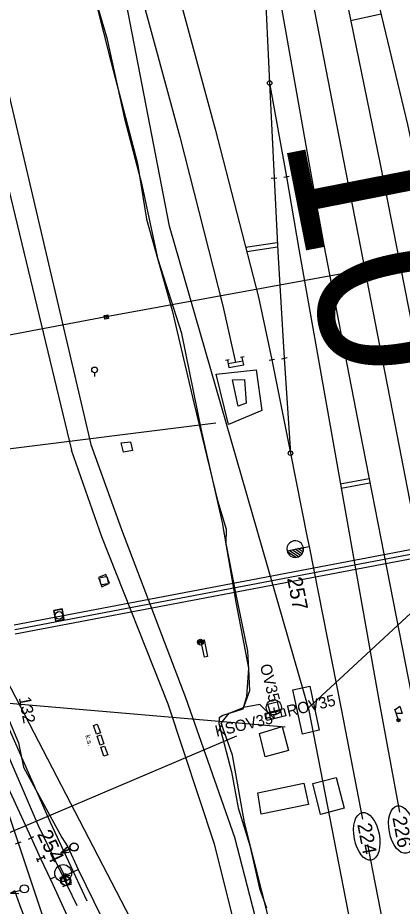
# Model space of a CAD drawing. Extents: x -545846 to -545044, y -1122650 to -1119108.
# Drawn here: x -545623.5 to -545572.5, y -1119607 to -1119489.2 of the extents above; entities that cross this region are included whole.
import ezdxf

# ---------------------------------------------------------------- set-up
doc = ezdxf.new("R2010")
doc.units = 0
for name, color, linetype in [('osvětlené plochy-hodnota-obrys', 7, 'Continuous'), ('Vrstva 1', 7, 'Continuous'), ('Vrstva 1 - Koleje', 7, 'Continuous'), ('Vrstva 11 - Trakce', 7, 'Continuous'), ('Vrstva 12', 7, 'Continuous'), ('Vrstva 12 - Trakce zaklady', 7, 'Continuous'), ('Vrstva 15', 7, 'Continuous'), ('Vrstva 19', 7, 'Continuous'), ('Vrstva 2', 7, 'Continuous'), ('Vrstva 2 - Vyhybky', 7, 'Continuous'), ('Vrstva 23', 7, 'Continuous'), ('Vrstva 25', 7, 'Continuous'), ('Vrstva 26', 7, 'Continuous'), ('Vrstva 27', 7, 'Continuous'), ('Vrstva 28 - zabzar', 7, 'Continuous'), ('Vrstva 3', 7, 'Continuous'), ('Vrstva 3 - Lisy - Pocitaci body', 7, 'Continuous'), ('Vrstva 31', 7, 'Continuous'), ('Vrstva 33', 7, 'Continuous'), ('Vrstva 36', 7, 'Continuous'), ('Vrstva 4 - Teren - stezky - prechody - plochy', 7, 'Continuous'), ('Vrstva 41', 7, 'Continuous'), ('Vrstva 43', 7, 'Continuous'), ('Vrstva 47', 7, 'Continuous'), ('Vrstva 51', 7, 'Continuous'), ('Vrstva 63', 7, 'Continuous'), ('Vrstva 7', 7, 'Continuous')]:
    doc.layers.add(name, color=color, linetype=linetype)

msp = doc.modelspace()

# ---------------------------------------------------------------- linework, layer by layer
at = {"layer": 'osvětlené plochy-hodnota-obrys'}
msp.add_line((-545562.16, -1119697.71), (-545631.88, -1119563.68), dxfattribs=at)
for points in [[(-545584.85, -1119581.02), (-545603.39, -1119516.8), (-545628.87, -1119385.18)], [(-545520.95, -1119506.89), (-545547.77, -1119546.31), (-545584.96, -1119580.66)], [(-545441.66, -1120319.91), (-545444.67, -1120302.28), (-545584.85, -1119581.02)]]:
    msp.add_lwpolyline(points, dxfattribs=at)
at = {"layer": 'Vrstva 1'}
msp.add_line((-545588.16, -1119534.32), (-545587.33, -1119546.92), dxfattribs=at)
for points in [[(-545599.51, -1119416.9), (-545596.69, -1119429.21), (-545596.41, -1119430.45), (-545593.93, -1119441.54), (-545591.16, -1119453.96), (-545590.21, -1119458.42), (-545589.95, -1119459.65), (-545585, -1119483.93), (-545580.04, -1119509.49), (-545578.33, -1119518.28), (-545575.84, -1119531.04)], [(-545620.21, -1119419.86), (-545619.43, -1119422.68), (-545612.37, -1119448.5), (-545606.52, -1119470.01), (-545604.5, -1119477.4), (-545597.32, -1119503.97), (-545591.58, -1119526.22), (-545589.81, -1119534.53)], [(-545624.75, -1119421.28), (-545624.13, -1119423.57), (-545617.27, -1119448.91), (-545611.27, -1119470.9), (-545609.21, -1119478.48), (-545602.01, -1119504.99), (-545596.3, -1119527.38), (-545594.62, -1119534.89)], [(-545593.93, -1119441.54), (-545592.82, -1119454.17), (-545592.44, -1119458.53), (-545592.33, -1119459.79), (-545592.3, -1119460.15), (-545592.2, -1119461.35), (-545591.2, -1119472.71), (-545589.02, -1119485.12), (-545584.57, -1119510.35), (-545582.9, -1119519.35), (-545580.39, -1119532.39)], [(-545589, -1119445.3), (-545586.24, -1119457.51), (-545586.1, -1119458.13), (-545580.77, -1119482.71), (-545575.45, -1119508.59), (-545573.77, -1119517.07), (-545571.21, -1119530.11)], [(-545580.06, -1119469.46), (-545577.13, -1119481.19), (-545571.82, -1119503.35), (-545568.95, -1119516.79), (-545566.49, -1119529.08)], [(-545591.2, -1119472.71), (-545590.69, -1119485.25), (-545590.64, -1119486.5), (-545590.1, -1119497.85), (-545589.52, -1119510.43), (-545589.02, -1119520.21), (-545588.16, -1119534.32)], [(-545590.1, -1119497.85), (-545587.86, -1119510.29), (-545586.21, -1119519.87), (-545583.87, -1119533.1)], [(-545575.84, -1119531.04), (-545573.5, -1119543.05), (-545570.17, -1119560.16), (-545566.74, -1119577.79), (-545563.84, -1119592.72)], [(-545583.87, -1119533.1), (-545581.83, -1119544.78), (-545578.74, -1119562.22), (-545575.63, -1119579.63), (-545572.9, -1119594.48)], [(-545580.39, -1119532.39), (-545578.14, -1119544.01), (-545574.96, -1119560.25), (-545571.36, -1119578.75), (-545568.45, -1119593.62)], [(-545589.81, -1119534.53), (-545587.33, -1119546.92), (-545585.11, -1119558.07), (-545584.87, -1119559.26)], [(-545584.87, -1119559.26), (-545580.63, -1119580.79), (-545577.77, -1119595.43)], [(-545577.12, -1119598.78), (-545576.45, -1119602.24), (-545572.16, -1119624.17), (-545568.47, -1119643.08), (-545563.87, -1119666.71), (-545559.47, -1119689.27)], [(-545619.18, -1119603.36), (-545619.11, -1119603.5)], [(-545619.12, -1119603.52), (-545618.83, -1119604.09), (-545613.93, -1119614.83), (-545607.84, -1119629.66)]]:
    msp.add_lwpolyline(points, dxfattribs=at)
for centre in [(-545572.58, -1119596.8), (-545577.23, -1119597.7)]:
    msp.add_ellipse(centre, major_axis=(0.61, -3.15), ratio=0.521067, dxfattribs=at)
at = {"layer": 'Vrstva 1 - Koleje'}
for points in [[(-545633.92, -1119567.08), (-545633.67, -1119567.82), (-545628.67, -1119582.84), (-545621.72, -1119597.89), (-545620.45, -1119600.64), (-545619.12, -1119603.52)], [(-545633.92, -1119567.08), (-545633.67, -1119567.82), (-545628.67, -1119582.84), (-545623.42, -1119598.57), (-545620.37, -1119607.69), (-545618.3, -1119613.58)]]:
    msp.add_lwpolyline(points, dxfattribs=at)
at = {"layer": 'Vrstva 12'}
for points in [[(-545608.56, -1119545.42), (-545608.28, -1119546.54), (-545609.48, -1119546.79), (-545609.78, -1119545.55)], [(-545612.8, -1119563.4), (-545612.35, -1119564.61), (-545611.32, -1119564.12), (-545611.82, -1119563)], [(-545590.71, -1119587.18), (-545591.46, -1119584.05), (-545588.42, -1119583.15), (-545587.58, -1119586.32)], [(-545580.21, -1119593.95), (-545583.35, -1119594.81), (-545584.39, -1119590.69), (-545581.26, -1119589.89)]]:
    msp.add_lwpolyline(points, close=True, dxfattribs=at)
msp.add_lwpolyline([(-545590.35, -1119580.17), (-545589.12, -1119579.86), (-545588.79, -1119581.1), (-545589.99, -1119581.39), (-545590.35, -1119580.17)], dxfattribs=at)
at = {"layer": 'Vrstva 12 - Trakce zaklady'}
msp.add_lwpolyline([(-545590.35, -1119580.17), (-545589.12, -1119579.86), (-545588.79, -1119581.1), (-545589.99, -1119581.39), (-545590.35, -1119580.17)], dxfattribs=at)
at = {"layer": 'Vrstva 15'}
for p, q in [((-545595.45, -1119534.54), (-545595.94, -1119534.64)), ((-545593.64, -1119534.7), (-545595.6, -1119535.08)), ((-545593.49, -1119534.16), (-545593.98, -1119534.25))]:
    msp.add_line(p, q, dxfattribs=at)
msp.add_lwpolyline([(-545595.69, -1119534.59), (-545595.5, -1119535.57), (-545593.54, -1119535.19), (-545593.73, -1119534.21)], dxfattribs=at)
for points in [[(-545591.9, -1119535.85), (-545591.13, -1119541.27), (-545595.57, -1119543.13), (-545597.2, -1119536.44)], [(-545595, -1119537.19), (-545593.42, -1119537.16), (-545593.19, -1119540.3), (-545594.27, -1119540.67)]]:
    msp.add_lwpolyline(points, close=True, dxfattribs=at)
at = {"layer": 'Vrstva 19'}
for p, q in [((-545493.78, -1119544.93), (-545623.98, -1119569.7)), ((-545623.85, -1119570.27), (-545493.72, -1119545.55)), ((-545493.53, -1119546.15), (-545623.83, -1119570.9))]:
    msp.add_line(p, q, dxfattribs=at)
at = {"layer": 'Vrstva 2'}
for p, q in [((-545590.1, -1119497.85), (-545587.86, -1119510.29)), ((-545589.89, -1119510.45), (-545589.14, -1119510.41)), ((-545587.49, -1119510.22), (-545588.23, -1119510.35)), ((-545590.18, -1119534.6), (-545589.44, -1119534.46)), ((-545588.52, -1119534.4), (-545587.79, -1119534.25)), ((-545588.16, -1119534.32), (-545587.33, -1119546.92)), ((-545587.78, -1119559.85), (-545584.87, -1119559.26)), ((-545587.78, -1119559.85), (-545585.63, -1119559.42)), ((-545587.78, -1119559.85), (-545587.78, -1119559.85)), ((-545586.64, -1119560.73), (-545587.74, -1119559.99)), ((-545586.26, -1119560.64), (-545587.52, -1119559.8)), ((-545586, -1119560.47), (-545587.13, -1119559.72)), ((-545585.81, -1119560.26), (-545586.73, -1119559.64)), ((-545585.68, -1119560), (-545586.34, -1119559.56)), ((-545585.61, -1119559.7), (-545585.94, -1119559.48)), ((-545617.94, -1119601.56), (-545617, -1119603.58)), ((-545618.5, -1119603.05), (-545619.18, -1119603.36))]:
    msp.add_line(p, q, dxfattribs=at)
for points in [[(-545590.69, -1119485.25), (-545590.64, -1119486.5), (-545590.1, -1119497.85), (-545589.52, -1119510.43)], [(-545589.81, -1119534.53), (-545587.33, -1119546.92), (-545585.11, -1119558.07), (-545584.87, -1119559.26)], [(-545619.11, -1119603.5), (-545618.83, -1119604.09), (-545613.93, -1119614.83), (-545607.84, -1119629.66)]]:
    msp.add_lwpolyline(points, dxfattribs=at)
for centre, radius in [((-545590.1, -1119497.85), 0.3), ((-545587.33, -1119546.92), 0.3), ((-545617.47, -1119602.57), 1.12)]:
    msp.add_circle(centre, radius, dxfattribs=at)
for start, end in [(11.2292, 191.6987), (191.3187, 11.2796)]:
    msp.add_arc((-545586.71, -1119559.63), 1.1, start, end, dxfattribs=at)
at = {"layer": 'Vrstva 2 - Vyhybky'}
for p, q in [((-545622.08, -1119598.06), (-545621.35, -1119597.73)), ((-545623.8, -1119598.7), (-545623.04, -1119598.44))]:
    msp.add_line(p, q, dxfattribs=at)
for points in [[(-545633.92, -1119567.08), (-545633.67, -1119567.82), (-545628.67, -1119582.84), (-545623.42, -1119598.57)], [(-545628.67, -1119582.84), (-545621.72, -1119597.89)]]:
    msp.add_lwpolyline(points, dxfattribs=at)
at = {"layer": 'Vrstva 23'}
for points in [[(-545599.24, -1119571.7), (-545598.77, -1119571.66), (-545598.32, -1119573.86), (-545598.75, -1119573.95)], [(-545584.79, -1119577.8), (-545583.52, -1119583.64), (-545585.74, -1119584.17), (-545587.04, -1119578.3)], [(-545591.22, -1119594.77), (-545591.66, -1119591.94), (-545585.56, -1119590.64), (-545584.95, -1119593.48)]]:
    msp.add_lwpolyline(points, close=True, dxfattribs=at)
at = {"layer": 'Vrstva 25'}
for points in [[(-545506.22, -1119509.73), (-545541.51, -1119516.04), (-545611.76, -1119528.86), (-545647.53, -1119535.61), (-545697.58, -1119544.77)], [(-545588.71, -1119580.89), (-545588.48, -1119581.86), (-545590.43, -1119582.33), (-545590.66, -1119581.36), (-545588.71, -1119580.89)], [(-545588.2, -1119580.76), (-545587.97, -1119581.73), (-545589.92, -1119582.2), (-545590.15, -1119581.23), (-545588.2, -1119580.76)]]:
    msp.add_lwpolyline(points, dxfattribs=at)
msp.add_circle((-545589.54, -1119580.6), 1, dxfattribs=at)
at = {"layer": 'Vrstva 26'}
for points in [[(-545593.58, -1119580.62), (-545593.12, -1119579.16), (-545592.86, -1119575.4), (-545594.55, -1119566.65), (-545596.34, -1119556.09), (-545599.08, -1119544.1), (-545601.73, -1119531.04), (-545604.88, -1119521.25), (-545606.99, -1119511.35), (-545609.25, -1119502.75), (-545611.6, -1119492.08), (-545613.72, -1119484.83), (-545615.02, -1119478.31), (-545615.38, -1119476.62)], [(-545578.2, -1119647.96), (-545580.46, -1119644.74), (-545582.9, -1119635.33), (-545585.07, -1119627.41), (-545588.38, -1119617.49), (-545589.97, -1119609.53), (-545593.41, -1119595.85), (-545595.04, -1119586.96), (-545596.51, -1119582.71), (-545595.46, -1119581.39), (-545593.58, -1119580.62)], [(-545589.54, -1119580.6), (-545589.54, -1119580.6), (-545589.53, -1119580.84), (-545589.3, -1119581.27), (-545589.06, -1119581.48), (-545589.57, -1119581.61), (-545589.49, -1119582.08), (-545591.41, -1119580.23), (-545593.58, -1119580.62)]]:
    msp.add_lwpolyline(points, dxfattribs=at)
at = {"layer": 'Vrstva 27'}
msp.add_line((-545617.18, -1119602.92), (-545617.2, -1119602.88), dxfattribs=at)
msp.add_circle((-545617.19, -1119602.9), 0.25, dxfattribs=at)
at = {"layer": 'Vrstva 28 - zabzar'}
msp.add_line((-545617.76, -1119599.93), (-545616.86, -1119599.1), dxfattribs=at)
for points in [[(-545642.06, -1119524.64), (-545640.63, -1119530.69), (-545639.91, -1119533.39), (-545637.75, -1119542.87), (-545634.65, -1119553.48), (-545633.29, -1119558.34), (-545631.9, -1119562.47), (-545630.58, -1119566.53), (-545627.3, -1119575.98), (-545623.39, -1119585.29), (-545622.71, -1119588.53), (-545617.63, -1119597.85), (-545616.86, -1119599.1), (-545615.46, -1119602.1), (-545610.32, -1119612.67), (-545606.39, -1119619.85), (-545601.98, -1119627.31), (-545600.79, -1119629.4), (-545602.25, -1119630.29), (-545602.73, -1119630.37), (-545602.6, -1119631.07)], [(-545617.19, -1119603.58), (-545617.19, -1119602.9), (-545615.46, -1119602.1)], [(-545602.41, -1119663.83), (-545602.8, -1119663.39), (-545603.89, -1119663.78), (-545604.71, -1119661.74), (-545605.8, -1119658.61), (-545607.17, -1119655.54), (-545608.43, -1119651.75), (-545609.58, -1119648.66), (-545612.26, -1119642.61), (-545614.17, -1119636.48), (-545616.81, -1119630.32), (-545617.94, -1119624.77), (-545618.68, -1119621.46), (-545618.67, -1119619.01), (-545619.98, -1119615.4), (-545621.7, -1119610.72), (-545623.18, -1119606.89), (-545623.86, -1119604.94), (-545624.45, -1119605.24)]]:
    msp.add_lwpolyline(points, dxfattribs=at)
at = {"layer": 'Vrstva 3'}
for p, q in [((-545617.78, -1119599.89), (-545616.98, -1119599.15)), ((-545617.78, -1119599.89), (-545616.52, -1119599.32)), ((-545621.01, -1119600.58), (-545620.81, -1119601.05)), ((-545619.99, -1119600.42), (-545620.91, -1119600.82)), ((-545620.09, -1119600.19), (-545619.89, -1119600.66)), ((-545617.78, -1119599.89), (-545616.7, -1119599.78)), ((-545616.59, -1119602.88), (-545617.79, -1119603.12)), ((-545617.19, -1119603), (-545616.95, -1119604.21)), ((-545616.35, -1119604.09), (-545617.56, -1119604.33))]:
    msp.add_line(p, q, dxfattribs=at)
for centre, radius in [((-545616.03, -1119599.1), 0.542), ((-545617.07, -1119603.61), 0.616)]:
    msp.add_circle(centre, radius, dxfattribs=at)
at = {"layer": 'Vrstva 3 - Lisy - Pocitaci body'}
for p, q in [((-545617.76, -1119599.93), (-545616.97, -1119599.18)), ((-545617.76, -1119599.93), (-545616.51, -1119599.35)), ((-545621.01, -1119600.62), (-545620.8, -1119601.08)), ((-545620, -1119600.43), (-545620.9, -1119600.85)), ((-545620.1, -1119600.21), (-545619.89, -1119600.66)), ((-545617.76, -1119599.93), (-545616.68, -1119599.81)), ((-545616.89, -1119602.76), (-545618.01, -1119603.28)), ((-545616.37, -1119603.88), (-545617.49, -1119604.4)), ((-545617.45, -1119603.02), (-545616.93, -1119604.14)), ((-545624.45, -1119605.24), (-545623.13, -1119604.82)), ((-545624.45, -1119605.24), (-545623.36, -1119605.26))]:
    msp.add_line(p, q, dxfattribs=at)
for centre, radius in [((-545616.01, -1119599.13), 0.542), ((-545617.19, -1119603.58), 0.616), ((-545622.62, -1119604.66), 0.542)]:
    msp.add_circle(centre, radius, dxfattribs=at)
at = {"layer": 'Vrstva 31'}
msp.add_lwpolyline([(-545615.07, -1119479.44), (-545611.37, -1119494.09), (-545607.62, -1119508.52), (-545606.43, -1119515.91), (-545603.02, -1119527.99), (-545600.16, -1119540.23), (-545597.03, -1119553.19), (-545595.85, -1119556.99), (-545595.91, -1119558.9), (-545594.65, -1119565.2), (-545593.05, -1119573.14), (-545592.88, -1119575.56), (-545592.75, -1119578.42), (-545593.65, -1119580.85), (-545596.32, -1119581.68), (-545596.77, -1119581.97), (-545596.83, -1119582.76), (-545595.14, -1119589.15), (-545594.27, -1119593.92), (-545592.73, -1119598.91), (-545591.43, -1119604.63), (-545590.52, -1119607.18)], dxfattribs=at)
at = {"layer": 'Vrstva 33'}
for p, q in [((-545573.49, -1119580.94), (-545572.86, -1119580.46)), ((-545572.86, -1119580.46), (-545572.54, -1119581.41)), ((-545573.54, -1119580.8), (-545573.09, -1119582.12)), ((-545572.54, -1119581.41), (-545573.33, -1119581.41)), ((-545573.18, -1119582.42), (-545573.03, -1119582.11)), ((-545573, -1119582.51), (-545572.85, -1119582.2))]:
    msp.add_line(p, q, dxfattribs=at)
msp.add_circle((-545573.02, -1119582.31), 0.2, dxfattribs=at)
msp.add_circle((-545573.02, -1119582.31), 0.2, dxfattribs=at)
at = {"layer": 'Vrstva 36'}
for p, q in [((-545612.04, -1119528.72), (-545611.52, -1119529.07)), ((-545612.04, -1119528.72), (-545611.52, -1119529.07)), ((-545611.83, -1119528.62), (-545611.51, -1119528.83)), ((-545611.83, -1119528.62), (-545611.51, -1119528.83)), ((-545611.99, -1119529), (-545611.8, -1119529.12)), ((-545611.99, -1119529), (-545611.8, -1119529.12)), ((-545613.3, -1119536.25), (-545613.3, -1119536.75)), ((-545613.3, -1119536.25), (-545613.3, -1119536.75))]:
    msp.add_line(p, q, dxfattribs=at)
msp.add_lwpolyline([(-545611.56, -1119528.57), (-545611.46, -1119529.06), (-545611.95, -1119529.15), (-545612.05, -1119528.66), (-545611.56, -1119528.57)], dxfattribs=at)
msp.add_lwpolyline([(-545611.56, -1119528.57), (-545611.46, -1119529.06), (-545611.95, -1119529.15), (-545612.05, -1119528.66), (-545611.56, -1119528.57)], dxfattribs=at)
for points in [[(-545613.06, -1119584.17), (-545613.46, -1119582.99), (-545612.97, -1119582.85), (-545612.52, -1119583.99)], [(-545612.58, -1119585.61), (-545612.98, -1119584.43), (-545612.46, -1119584.26), (-545612.06, -1119585.45)], [(-545612.07, -1119587.07), (-545612.48, -1119585.9), (-545611.98, -1119585.75), (-545611.56, -1119586.91)]]:
    msp.add_lwpolyline(points, close=True, dxfattribs=at)
msp.add_circle((-545613.3, -1119535.87), 0.378, dxfattribs=at)
msp.add_circle((-545613.3, -1119535.87), 0.378, dxfattribs=at)
at = {"layer": 'Vrstva 4 - Teren - stezky - prechody - plochy'}
for points in [[(-545658.88, -1119493.55), (-545657.16, -1119493.29), (-545652.41, -1119492.3), (-545652.64, -1119491.29), (-545650.37, -1119490.81), (-545647.98, -1119490.64), (-545647.02, -1119490.55), (-545646.4, -1119493.56), (-545647.33, -1119493.82), (-545645.82, -1119500.74), (-545643.4, -1119514.85), (-545641.38, -1119525.06), (-545641.37, -1119525.07), (-545641.18, -1119529.07), (-545640.19, -1119530.53), (-545638.6, -1119538.62), (-545635.76, -1119550.16), (-545633.18, -1119559.27), (-545632.8, -1119560.65), (-545629.37, -1119570.84), (-545625.13, -1119582.37), (-545619.18, -1119595.83), (-545614.31, -1119606.24)], [(-545647.98, -1119490.64), (-545647.02, -1119490.55), (-545646.4, -1119493.56), (-545647.33, -1119493.82), (-545645.82, -1119500.74), (-545643.4, -1119514.85), (-545641.38, -1119525.06), (-545641.37, -1119525.07), (-545641.18, -1119529.07), (-545640.19, -1119530.53), (-545638.6, -1119538.62), (-545635.76, -1119550.16), (-545633.18, -1119559.27), (-545632.8, -1119560.65), (-545629.37, -1119570.84), (-545625.13, -1119582.37), (-545619.18, -1119595.83), (-545614.31, -1119606.24)], [(-545647.98, -1119490.64), (-545646.63, -1119503.49), (-545644.84, -1119514.96), (-545642.93, -1119525.85), (-545639.99, -1119539.47), (-545637.31, -1119550.22), (-545633.98, -1119561.6), (-545630.95, -1119570.87), (-545626.32, -1119583.51), (-545620.8, -1119596.26), (-545615.65, -1119606.86)]]:
    msp.add_lwpolyline(points, dxfattribs=at)
at = {"layer": 'Vrstva 41'}
for p, q in [((-545612.48, -1119564.27), (-545612.61, -1119563.54)), ((-545612.51, -1119563.39), (-545611.78, -1119563.25)), ((-545611.63, -1119563.35), (-545611.49, -1119564.09)), ((-545611.59, -1119564.24), (-545612.33, -1119564.37))]:
    msp.add_line(p, q, dxfattribs=at)
at = {"layer": 'Vrstva 43'}
msp.add_circle((-545618.02, -1119568.41), 0.5, dxfattribs=at)
at = {"layer": 'Vrstva 47'}
for points in [[(-545618.45, -1119569.19), (-545618.71, -1119567.77), (-545617.6, -1119567.59), (-545617.38, -1119568.95)], [(-545618.45, -1119569.17), (-545617.43, -1119568.96), (-545617.59, -1119567.56), (-545618.69, -1119567.78)]]:
    msp.add_lwpolyline(points, close=True, dxfattribs=at)
for points in [[(-545617.59, -1119567.56), (-545617.6, -1119567.59)], [(-545618.69, -1119567.78), (-545618.71, -1119567.77)], [(-545618.45, -1119569.19), (-545618.45, -1119569.17)], [(-545617.43, -1119568.96), (-545617.38, -1119568.95)]]:
    msp.add_lwpolyline(points, dxfattribs=at)
at = {"layer": 'Vrstva 51'}
for points in [[(-545654.71, -1119405.94), (-545655.51, -1119411.12), (-545652.93, -1119414), (-545647.83, -1119421.35), (-545641.98, -1119434.03), (-545634.09, -1119468.04), (-545630.81, -1119484.54), (-545628.49, -1119498.88), (-545628.2, -1119500.25), (-545627.6, -1119500.06), (-545616.37, -1119546.5)], [(-545654.71, -1119405.94), (-545651.83, -1119408.92), (-545645.29, -1119419.91), (-545639.14, -1119433.19), (-545631.2, -1119467.37), (-545627.71, -1119485.1), (-545624.68, -1119499.39), (-545613.78, -1119545.76)], [(-545613.78, -1119545.76), (-545609.74, -1119557.01), (-545601.23, -1119579.3), (-545594.76, -1119597.8), (-545591.11, -1119611.99), (-545593.8, -1119613.18), (-545597.41, -1119598.72), (-545603.57, -1119580.18), (-545612.32, -1119558), (-545616.37, -1119546.5)]]:
    msp.add_lwpolyline(points, dxfattribs=at)
at = {"layer": 'Vrstva 63'}
for p, q in [((-545597.23, -1119542.92), (-545692.49, -1119554.94)), ((-545599.64, -1119571.99), (-545599.44, -1119571.78)), ((-545599.64, -1119571.99), (-545599.44, -1119571.78)), ((-545599.59, -1119572.15), (-545599.33, -1119571.89)), ((-545599.59, -1119572.15), (-545599.33, -1119571.89)), ((-545599.53, -1119572.23), (-545598.99, -1119571.68)), ((-545599.53, -1119572.23), (-545598.99, -1119571.68)), ((-545599.53, -1119571.69), (-545599.26, -1119571.96)), ((-545599.53, -1119571.69), (-545598.99, -1119572.23)), ((-545599.53, -1119571.69), (-545599.26, -1119571.96)), ((-545599.53, -1119571.69), (-545598.99, -1119572.23)), ((-545599.26, -1119571.96), (-545599.53, -1119572.23)), ((-545599.26, -1119571.96), (-545599.53, -1119572.23)), ((-545599.26, -1119571.96), (-545599.53, -1119572.23)), ((-545599.26, -1119571.96), (-545599.53, -1119572.23)), ((-545599.26, -1119571.96), (-545598.99, -1119571.68)), ((-545599.26, -1119571.96), (-545598.99, -1119571.68)), ((-545599.26, -1119571.96), (-545598.99, -1119572.23)), ((-545598.99, -1119572.23), (-545599.26, -1119571.96)), ((-545599.26, -1119571.96), (-545598.99, -1119572.23)), ((-545598.99, -1119572.23), (-545599.26, -1119571.96)), ((-545599.19, -1119572.03), (-545598.93, -1119571.77)), ((-545599.19, -1119572.03), (-545598.93, -1119571.77)), ((-545599.08, -1119572.14), (-545598.88, -1119571.93)), ((-545599.08, -1119572.14), (-545598.88, -1119571.93)), ((-545588.03, -1119583.24), (-545688.63, -1119574.64)), ((-545594.49, -1119584.44), (-545679.64, -1119620.55))]:
    msp.add_line(p, q, dxfattribs=at)
msp.add_circle((-545599.26, -1119571.96), 0.382, dxfattribs=at)
msp.add_circle((-545599.26, -1119571.96), 0.382, dxfattribs=at)
for radius, start, end in [(0.382, 134.523, 224.841), (0.382, 134.523, 224.841), (0.383, 315.2118, 45.1053), (0.383, 315.2118, 45.1053)]:
    msp.add_arc((-545599.26, -1119571.96), radius, start, end, dxfattribs=at)
at = {"layer": 'Vrstva 7'}
for p, q in [((-545579.36, -1119489.57), (-545575.33, -1119488.67)), ((-545593.28, -1119519.62), (-545589.08, -1119518.98)), ((-545593.13, -1119520.2), (-545589.05, -1119519.58)), ((-545580.74, -1119550.96), (-545576.92, -1119550.25)), ((-545580.63, -1119551.55), (-545576.8, -1119550.84))]:
    msp.add_line(p, q, dxfattribs=at)

# ---------------------------------------------------------------- texts
at = {"layer": 'osvětlené plochy-hodnota-obrys'}
msp.add_text('10', height=22.781, rotation=281.0956, dxfattribs=at).set_placement((-545588.24, -1119504.87))
at = {"layer": 'Vrstva 1'}
for s, p in [('226', (-545573.84, -1119595.22)), ('224', (-545578.49, -1119596.12))]:
    msp.add_text(s, height=1.875, rotation=280.9117, dxfattribs=at).set_placement(p)
at = {"layer": 'Vrstva 11 - Trakce'}
msp.add_text('132', height=1.6, rotation=280.644, dxfattribs=at).set_placement((-545623.36, -1119579.33))
at = {"layer": 'Vrstva 2'}
for s, rotation, p in [('257', 281.0315, (-545587.8, -1119563.5)), ('254', 295.5018, (-545620.96, -1119597.4))]:
    msp.add_text(s, height=2, rotation=rotation, dxfattribs=at).set_placement(p)
at = {"layer": 'Vrstva 25'}
for s, rotation, p in [('OV35', 284.2438, (-545591.4, -1119575.05)), ('ROV35', 13.5409, (-545587.64, -1119581.87)), ('KSOV35', 13.5409, (-545597.13, -1119584.52))]:
    msp.add_text(s, height=1.5, rotation=rotation, dxfattribs=at).set_placement(p)
at = {"layer": 'Vrstva 63'}
msp.add_text('k.s.', height=0.695, rotation=286.4026, dxfattribs=at).set_placement((-545614.57, -1119584.35))
msp.add_text('k.s.', height=0.695, rotation=286.4026, dxfattribs=at).set_placement((-545614.57, -1119584.35))

doc.saveas('drawing.dxf')
